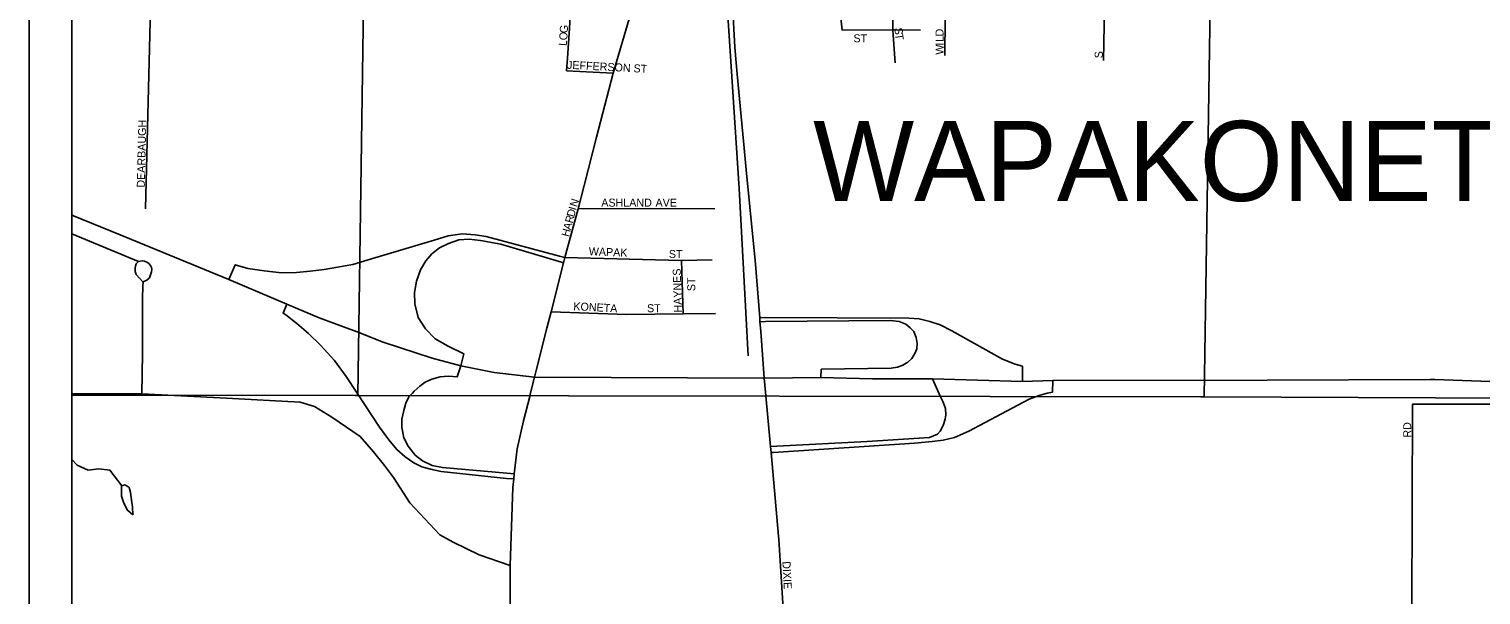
# Model space of a CAD drawing. Extents: x -784 to 1375, y -225 to 440.
# Drawn here: x 65.1 to 133.1, y 308 to 334.5 of the extents above; entities that cross this region are included whole.
import ezdxf

# ---------------------------------------------------------------- set-up
doc = ezdxf.new("R2010")
doc.units = 0
for name, color, linetype in [('GM_X_City_Street', 7, 'Continuous'), ('GM_X_City_Street_Text', 7, 'Continuous'), ('GM_X_Corporation_Text', 7, 'Continuous'), ('GM_X_County_Road', 7, 'Continuous'), ('GM_X_Interchange_Ramps', 7, 'Continuous'), ('GM_X_Minor_Lake', 7, 'Continuous'), ('GM_X_Minor_River', 7, 'Continuous'), ('GM_X_Rail_Line', 7, 'Continuous'), ('GM_X_Section', 7, 'Continuous'), ('GM_X_State_Route', 7, 'Continuous'), ('GM_X_US_Route', 7, 'Continuous'), ('SH_Data', 7, 'Continuous'), ('SH_Text', 7, 'Continuous')]:
    doc.layers.add(name, color=color, linetype=linetype)

msp = doc.modelspace()

# ---------------------------------------------------------------- linework, layer by layer
at = {"layer": 'GM_X_City_Street'}
for points in [[(91.68, 329.482), (92.456, 332.472), (93.284, 335.289), (93.372, 335.892), (93.537, 338.077), (93.645, 340.796), (94.021, 346.476), (94.217, 349.327), (94.405, 352.212), (94.511, 354.091), (94.544, 355.08), (94.584, 355.669), (94.642, 356.682), (94.812, 358.8), (94.853, 359.554)], [(115.42, 333.071), (115.698, 347.082), (115.743, 348.168), (115.768, 349.599), (115.762, 350.978)], [(103.18, 334.498), (103.091, 335.341), (103.129, 336.893), (103.161, 340.33), (103.18, 340.924), (103.193, 341.722), (103.198, 341.863)], [(70.541, 326.113), (70.822, 337.425)], [(105.57, 334.261), (105.55, 334.504), (105.576, 336.855)], [(90.262, 332.585), (90.311, 333.189), (90.403, 334.593), (90.455, 335.426)], [(107.991, 333.309), (108.016, 335.047)], [(103.18, 334.498), (105.55, 334.504), (105.629, 334.503)], [(105.672, 332.968), (105.57, 334.261)], [(105.629, 334.503), (106.854, 334.491)], [(90.262, 332.585), (92.456, 332.472)], [(91.092, 327.219), (91.68, 329.482)], [(89.353, 320.524), (89.545, 321.284), (90.132, 323.586), (90.191, 323.83), (90.808, 326.125), (91.092, 327.219)], [(90.808, 326.125), (94.202, 326.14), (97.223, 326.121)], [(90.191, 323.83), (95.659, 323.698), (97.086, 323.73)], [(95.734, 321.192), (95.659, 323.698)], [(89.545, 321.284), (93.075, 321.172), (95.734, 321.192), (97.255, 321.204)], [(129.862, 302.524), (129.911, 316.968), (134.73, 316.967), (135.85, 316.872), (138.098, 316.511), (139.727, 316.14), (141.314, 315.604), (142.118, 314.974), (144.593, 312.499), (144.675, 301.856), (146.016, 301.248)], [(100.206, 310.775), (99.852, 314.69), (99.826, 314.974)], [(100.428, 307.245), (100.412, 307.367), (100.218, 310.635), (100.206, 310.775)]]:
    msp.add_lwpolyline(points, dxfattribs=at)
at = {"layer": 'GM_X_County_Road'}
msp.add_line((67.088, 324.939), (70.215, 323.646), dxfattribs=at)
for points in [[(70.368, 317.449), (70.408, 319.331), (70.411, 321.912), (70.423, 322.491), (70.428, 322.693), (70.612, 322.769), (70.73, 322.888), (70.823, 323.16), (70.836, 323.296), (70.827, 323.374), (70.781, 323.466), (70.696, 323.551), (70.611, 323.619), (70.5, 323.67), (70.394, 323.674), (70.215, 323.646), (70.105, 323.546), (70.075, 323.453), (70.059, 323.342), (70.054, 323.312), (70.059, 323.253), (70.067, 323.185), (70.11, 323.045), (70.427, 322.693)], [(88.87, 318.609), (89.353, 320.524)], [(88.546, 317.326), (88.589, 317.496), (88.773, 318.226), (88.87, 318.609)], [(67.088, 317.44), (70.368, 317.449), (74.333, 317.238)], [(74.333, 317.238), (77.794, 317.054), (78.467, 316.845), (79.279, 316.358), (80.601, 315.452), (81.228, 314.733), (81.738, 314.083), (82.156, 313.526), (82.922, 312.342), (84.337, 310.833), (84.964, 310.497), (86.17, 309.905), (87.632, 309.394)], [(87.795, 313.454), (87.822, 313.689), (87.957, 314.872), (88.258, 316.183), (88.546, 317.326)], [(87.532, 306.646), (87.551, 306.847), (87.571, 307.056), (87.627, 307.646), (87.632, 309.394), (87.748, 313.05), (87.795, 313.454)]]:
    msp.add_lwpolyline(points, dxfattribs=at)
at = {"layer": 'GM_X_Interchange_Ramps'}
for points in [[(90.191, 323.83), (89.938, 323.9), (86.511, 324.817), (85.988, 324.906), (85.377, 324.94), (84.72, 324.853), (84.075, 324.657), (80.976, 323.734), (80.253, 323.514), (79.543, 323.377), (78.916, 323.278), (78.259, 323.19), (77.614, 323.134), (76.913, 323.114), (76.097, 323.207), (75.343, 323.329), (74.752, 323.494), (74.456, 322.801)], [(85.317, 318.757), (85.455, 319.326), (84.721, 319.68), (84.119, 320.023), (83.665, 320.486), (83.326, 321.027), (83.161, 321.661), (83.152, 322.202), (83.241, 322.725), (83.423, 323.265), (83.678, 323.675), (83.956, 324.006), (84.321, 324.288), (84.744, 324.496), (85.224, 324.667), (85.704, 324.698), (86.237, 324.64), (87.195, 324.46), (89.93, 323.643), (90.132, 323.586)], [(77.167, 321.646), (76.988, 321.227), (77.123, 321.145), (77.636, 320.747), (78.188, 320.267), (78.737, 319.734), (79.404, 319.002), (79.948, 318.264), (80.463, 317.475), (81.5, 315.886), (81.94, 315.29), (82.312, 314.84), (82.703, 314.488), (83.121, 314.212), (83.486, 314.026), (83.895, 313.91), (84.396, 313.812), (87.451, 313.484), (87.795, 313.454)], [(111.629, 318.03), (111.626, 318.736), (111.292, 318.843), (110.692, 319.077), (108.329, 320.406), (107.779, 320.673), (107.292, 320.841), (106.789, 320.96), (106.301, 320.998), (99.594, 321.023), (99.319, 321.002)], [(99.332, 320.824), (99.592, 320.844), (105.453, 320.877), (105.86, 320.84), (106.168, 320.706), (106.377, 320.541), (106.538, 320.361), (106.649, 320.082), (106.695, 319.805), (106.676, 319.561), (106.592, 319.334), (106.443, 319.108), (106.262, 318.93), (106.032, 318.786), (105.771, 318.691), (105.477, 318.646), (102.204, 318.6), (102.184, 318.213)], [(87.822, 313.689), (87.469, 313.72), (84.464, 313.995), (83.977, 314.087), (83.521, 314.308), (83.184, 314.571), (82.852, 314.988), (82.654, 315.391), (82.55, 315.863), (82.558, 316.26), (82.653, 316.659), (82.746, 317.006), (82.889, 317.3), (83.047, 317.482), (83.13, 317.576), (83.405, 317.805), (83.648, 317.993), (83.961, 318.138), (84.346, 318.239), (84.723, 318.273), (85.144, 318.239), (85.146, 318.239), (85.317, 318.757)], [(99.852, 314.69), (99.964, 314.7), (106.578, 315.132), (107.393, 315.205), (107.915, 315.28), (108.454, 315.405), (109.124, 315.69), (111.417, 316.919), (111.95, 317.194), (112.415, 317.364), (112.791, 317.474), (113.044, 317.524), (113.054, 318.07)]]:
    msp.add_lwpolyline(points, dxfattribs=at)
at = {"layer": 'GM_X_Minor_Lake'}
for points in [[(69.592, 313.179), (69.424, 313.137), (69.418, 312.641), (69.534, 312.324), (69.709, 311.991), (69.947, 311.778)], [(69.947, 311.778), (69.937, 312.154), (69.909, 312.349), (69.841, 312.816), (69.784, 313.057), (69.592, 313.179)]]:
    msp.add_lwpolyline(points, dxfattribs=at)
at = {"layer": 'GM_X_Minor_River'}
msp.add_lwpolyline([(67.088, 314.373), (67.349, 314.097), (67.857, 313.865), (68.353, 313.933), (68.878, 313.866), (69.43, 313.139)], dxfattribs=at)
at = {"layer": 'GM_X_Rail_Line'}
msp.add_lwpolyline([(98.775, 319.233), (98.355, 327.064), (97.622, 338.297), (97.613, 339.578), (97.673, 340.741), (97.75, 341.835), (97.878, 342.698), (98.049, 343.561)], dxfattribs=at)
at = {"layer": 'GM_X_Section'}
msp.add_lwpolyline([(67.088, 357.38), (67.104, 357.38), (67.222, 357.273), (67.443, 357.028), (67.648, 356.785), (67.855, 356.616), (68.019, 356.568), (68.303, 356.532), (68.872, 356.446), (69.59, 356.358), (69.875, 356.368), (70.329, 356.554), (70.648, 356.788), (71.183, 357.303), (71.441, 357.464), (81.068, 357.283), (80.486, 317.362), (80.366, 317.364), (67.088, 317.379)], dxfattribs=at)
for points in [[(81.068, 357.283), (120.755, 357.05), (120.146, 317.31), (119.981, 317.313), (80.486, 317.362)], [(120.755, 357.05), (160.697, 356.887), (159.863, 317.136), (120.146, 317.31)]]:
    msp.add_lwpolyline(points, close=True, dxfattribs=at)
at = {"layer": 'GM_X_State_Route'}
for points in [[(98.221, 332.97), (98.159, 333.692), (98.045, 335.698), (97.987, 336.937), (97.993, 337.513), (98.025, 338.203), (98.196, 340.627), (98.409, 344.193)], [(98.693, 327.952), (98.643, 328.464), (98.267, 332.435), (98.221, 332.97)], [(99.036, 324.48), (98.693, 327.952)], [(99.23, 322.162), (99.111, 323.718), (99.036, 324.48)], [(99.366, 320.384), (99.332, 320.824), (99.319, 321.002), (99.23, 322.162)], [(99.536, 318.182), (99.366, 320.384)], [(99.826, 314.974), (99.595, 317.524), (99.536, 318.182)], [(107.422, 318.152), (107.789, 317.305), (107.923, 317.048), (108.027, 316.758), (108.041, 316.455), (108.015, 316.259), (107.911, 315.969), (107.772, 315.702), (107.645, 315.56), (107.281, 315.402), (104.357, 315.212), (99.826, 314.974)]]:
    msp.add_lwpolyline(points, dxfattribs=at)
at = {"layer": 'GM_X_US_Route'}
msp.add_line((67.088, 325.821), (69.353, 324.892), dxfattribs=at)
for points in [[(69.353, 324.892), (74.456, 322.801), (77.167, 321.646), (78.681, 321.001), (79.824, 320.593), (80.459, 320.345)], [(80.459, 320.345), (81.683, 319.865), (83.972, 319.111), (85.317, 318.757), (86.883, 318.448), (88.773, 318.226), (99.536, 318.182)], [(99.536, 318.182), (102.184, 318.213), (104.606, 318.152), (104.887, 318.152)], [(104.887, 318.152), (107.422, 318.152)], [(107.422, 318.152), (111.629, 318.03), (113.054, 318.07), (123.097, 318.093)], [(123.097, 318.093), (130.73, 318.111)], [(130.73, 318.111), (130.951, 318.111), (133.972, 318.009), (137.293, 317.66), (138.45, 317.389), (140.273, 316.969), (143.494, 316.228), (146.387, 315.562), (148.845, 314.996), (149.595, 314.936)]]:
    msp.add_lwpolyline(points, dxfattribs=at)
at = {"layer": 'SH_Data'}
msp.add_line((65.088, 421.485), (65.088, 281.485), dxfattribs=at)
at = {"layer": 'SH_Text'}
msp.add_lwpolyline([(67.088, 419.485), (203.088, 419.485), (203.088, 283.485), (67.088, 283.485)], close=True, dxfattribs=at)

# ---------------------------------------------------------------- texts
at = {"layer": 'GM_X_City_Street_Text'}
for s, rotation, p in [('G', 86.49143, (90.322, 334.344)), ('L', 85.65158, (90.277, 333.745)), ('O', 85.64655, (90.297, 334.009)), ('ST', 0.00001, (103.712, 333.925)), ('S', 274.81921, (105.634, 334.597)), ('T', 278.00012, (105.659, 334.311)), ('D', 89.97034, (107.932, 334.202)), ('L', 89.97267, (107.932, 333.938)), ('I', 89.98499, (107.932, 333.773)), ('W', 89.96637, (107.932, 333.344)), ('S', 90, (115.39, 333.179)), ('JEFFERSON ST', 356.95682, (90.285, 332.688)), ('DEARBAUGH', 88.68383, (70.51, 327.109)), ('N', 72.00051, (90.759, 326.178)), ('ASHLAND', 0.00001, (91.898, 326.221)), ('AVE', 0.00001, (94.439, 326.221)), ('D', 74.91933, (90.628, 325.706)), ('I', 73.45991, (90.713, 326.022)), ('H', 74.94611, (90.379, 324.782)), ('A', 74.96774, (90.465, 325.101)), ('R', 74.93872, (90.551, 325.419)), ('WAPAK', 357.75543, (91.307, 323.944)), ('ST', 0.00001, (95.066, 323.812)), ('HAYNES', 92.0443, (95.689, 321.264)), ('ST', 90, (96.301, 322.256)), ('KONETA', 356.98882, (90.582, 321.37)), ('ST', 0.00001, (94.043, 321.271)), ('RD', 90, (129.844, 315.392)), ('DIXIE', 273.01687, (100.384, 309.588))]:
    msp.add_text(s, height=0.375, rotation=rotation, dxfattribs=at).set_placement(p)
at = {"layer": 'GM_X_Corporation_Text'}
msp.add_text('WAPAKONETA', height=3.75, rotation=0.00001, dxfattribs=at).set_placement((101.822, 326.489))

doc.saveas('drawing.dxf')
